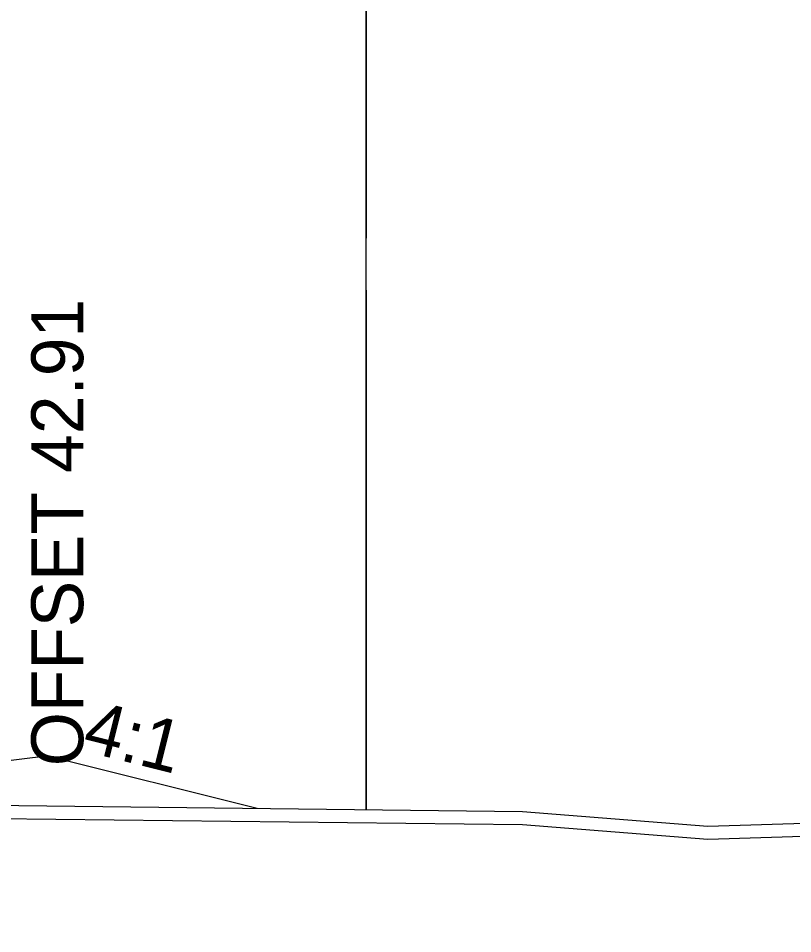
# Model space of a CAD drawing. Extents: x 1574 to 14903, y 7971 to 16537.
# Drawn here: x 4843.66 to 4858.57, y 11001.01 to 11018.63 of the extents above; entities that cross this region are included whole.
import ezdxf

# ---------------------------------------------------------------- set-up
doc = ezdxf.new("R2010")
doc.units = 0
for name, color, linetype in [('DESIGN - ROW - Right-of-Way Linework', 7, 'Continuous'), ('DESIGN - SCRATCH - User 2', 7, 'Continuous'), ('DESIGN - TYPICAL - Slope Tie Text', 7, 'Continuous'), ('SURVEY - GROUND - Bottom of Topsoil Layer', 7, 'Continuous'), ('SURVEY - GROUND - Top of Ground', 7, 'Continuous'), ('SURVEY - PROPERTY - ROW Lines', 7, 'Continuous')]:
    doc.layers.add(name, color=color, linetype=linetype)

msp = doc.modelspace()

# ---------------------------------------------------------------- linework, layer by layer
at = {"layer": 'DESIGN - ROW - Right-of-Way Linework'}
msp.add_line((4850.363, 11003.399), (4850.363, 11035.399), dxfattribs=at)
at = {"layer": 'DESIGN - SCRATCH - User 2'}
for p in [(4835, 11003.29), (4848.263, 11003.424)]:
    msp.add_line(p, (4844.2, 11004.44), dxfattribs=at)
at = {"layer": 'SURVEY - GROUND - Bottom of Topsoil Layer'}
for p, q in [((4840.968, 11003.261), (4853.368, 11003.114)), ((4853.368, 11003.114), (4856.937, 11002.831)), ((4856.937, 11002.831), (4865.617, 11003.101))]:
    msp.add_line(p, q, dxfattribs=at)
at = {"layer": 'SURVEY - GROUND - Top of Ground'}
msp.add_lwpolyline([(4772.921, 11001.245), (4779.039, 11001.435), (4784.985, 11001.704), (4787.046, 11001.469), (4787.607, 11001.362), (4790.684, 11001.014), (4800, 11001.196), (4804.715, 11001.288), (4811.815, 11001.254), (4813.929, 11001.197), (4814.613, 11001.3), (4816.97, 11001.723), (4818.933, 11002.092), (4822.384, 11002.61), (4823.984, 11002.842), (4829.464, 11003.114), (4833.685, 11003.246), (4840.968, 11003.511), (4853.368, 11003.364), (4856.937, 11003.081), (4865.617, 11003.351)], dxfattribs=at)
at = {"layer": 'SURVEY - PROPERTY - ROW Lines'}
for p, q in [((4850.364, 11014.399), (4850.364, 11024.399)), ((4850.364, 11003.399), (4850.364, 11013.399))]:
    msp.add_line(p, q, dxfattribs=at)

# ---------------------------------------------------------------- texts
at = {"layer": 'DESIGN - SCRATCH - User 2'}
msp.add_text('4:1', height=1, rotation=345.9638, dxfattribs=at).set_placement((4844.863, 11004.541))
at = {"layer": 'DESIGN - TYPICAL - Slope Tie Text'}
msp.add_text('OFFSET 42.91', height=1, rotation=90, dxfattribs=at).set_placement((4844.911, 11004.238))

doc.saveas('drawing.dxf')
